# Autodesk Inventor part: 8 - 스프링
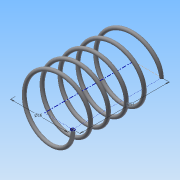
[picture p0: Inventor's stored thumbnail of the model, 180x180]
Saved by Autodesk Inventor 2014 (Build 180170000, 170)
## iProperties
Created: 2015-06
Part Number: 8 - 스프링
Material: 강철, 연강
Document SubType Name: Modeling
Designer: Administrator
Density: 7.86 g/cm^3
Appearance: 강철
Mass: 1.53535 g
Surface Area: 7.89042 cm^2
Volume: 0.195337 cm^3
Author: Administrator
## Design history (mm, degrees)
sketch "스케치1"
  geometry: L1 (0, 0)-(8, 0); L2 (8, 0)-(8, 21.5); L3 (8, 21.5)-(0, 21.5); L4 (0, 21.5)-(0, 0); C1 r 0.5 at (8, 0)
  constraints: 8 end point, 2 parallel, 1 centre point, 1 coincident, 1 horizontal, 1 perpendicular
  dimensions: "d1" = 1 diameter of C1; "d2" = 16 diameter of L2 L4; "d3" = 21.5 distance of L1.end L2.end (derived)
feature "코일1" sketch "스케치1" pitch "d4" = 10; turns "d6" = 5; dims "d5" = 21.5 (= d3), "d7" = 0, angle "d8" = 90 deg, angle "d9" = 90 deg, "d10" = 0, "d11" = 0
sketch "스케치2"
  geometry: L1 (-8.5, 0)-(-7.5, 0) reference; 1 further point
  constraints: 1 horizontal alignment
extrude "돌출1" cut sketch "스케치2" stored distance "d12" = 10; taper "d13" = 0 deg
node "작업 평면1"
sketch "스케치3"
  geometry: L1 (8.5, 0)-(7.5, 0) reference; 1 further point
  constraints: 1 horizontal alignment
extrude "돌출2" cut sketch "스케치3" stored distance "d15" = 10; taper "d16" = 0 deg
node "솔리드1"
node "절단 모서리 투영1"
node "절단 모서리 투영2"
other parameters: "d14" = -21.5 (= -d3)
